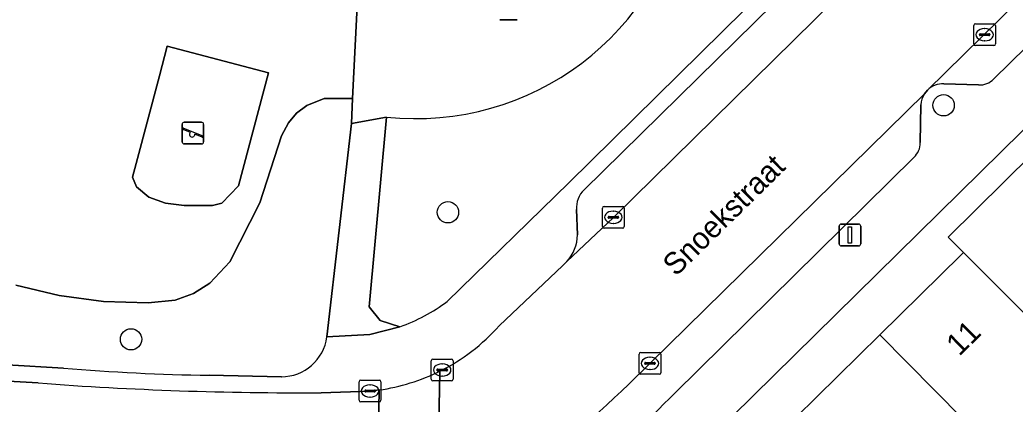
# Model space of a CAD drawing. Extents: x 160102 to 160934, y 382045 to 382923.
# Drawn here: x 160580.16 to 160625.81, y 382618.63 to 382636.26 of the extents above; entities that cross this region are included whole.
import ezdxf

# ---------------------------------------------------------------- set-up
doc = ezdxf.new("R2010")
doc.units = 0
for name, color, linetype in [('IMGEO_Boom', 7, 'Continuous'), ('IMGEO_Erf', 7, 'Continuous'), ('IMGEO_Groenvoorziening', 7, 'Continuous'), ('IMGEO_Kolk', 7, 'Continuous'), ('IMGEO_Lichtmast', 7, 'Continuous'), ('IMGEO_Openbare_ruimte_label', 7, 'Continuous'), ('IMGEO_Pand', 7, 'Continuous'), ('IMGEO_Pand_nummerreeks', 7, 'Continuous'), ('IMGEO_Parkeervlak_open', 7, 'Continuous'), ('IMGEO_Rijbaan_lokaal_open', 7, 'Continuous'), ('IMGEO_Speelvoorziening', 7, 'Continuous'), ('IMGEO_Terreindeel_zand', 7, 'Continuous'), ('IMGEO_Voetpad_open', 7, 'Continuous')]:
    doc.layers.add(name, color=color, linetype=linetype)

msp = doc.modelspace()

# ---------------------------------------------------------------- linework, layer by layer
at = {"layer": 'IMGEO_Boom'}
for centre in [(160622.528, 382632.346), (160599.793, 382627.438), (160585.259, 382621.606)]:
    msp.add_circle(centre, 0.489, dxfattribs=at)
at = {"layer": 'IMGEO_Erf'}
for points in [[(160661.762, 382636.708), (160646.97, 382651.686), (160602.42, 382607.815), (160569.084, 382609.884)], [(160615.748, 382618.012), (160619.597, 382621.808), (160623.314, 382625.474), (160623.44, 382625.598), (160622.74, 382626.3), (160626.598, 382630.102), (160630.432, 382633.883), (160634.268, 382637.664), (160638.105, 382641.447), (160641.954, 382645.241), (160645.935, 382649.166), (160652.312, 382642.745), (160648.748, 382639.239), (160648.326, 382638.824), (160644.465, 382635.025), (160640.62, 382631.244), (160636.792, 382627.478), (160632.941, 382623.689), (160635.111, 382621.515), (160631.378, 382617.789)]]:
    msp.add_lwpolyline(points, dxfattribs=at)
at = {"layer": 'IMGEO_Groenvoorziening'}
for points in [[(160599.766, 382623.349), (160605.335, 382628.789), (160619.427, 382642.677), (160618.419, 382643.7)], [(160579.978, 382624.096), (160581.967, 382623.615), (160583.995, 382623.344), (160586.041, 382623.287), (160587.285, 382623.409), (160588.122, 382623.714), (160588.878, 382624.187), (160589.787, 382625.163), (160591.169, 382627.872), (160592.162, 382630.942), (160592.478, 382631.541), (160592.856, 382631.979), (160593.316, 382632.329), (160594.118, 382632.656), (160595.423, 382632.661), (160595.751, 382639.325), (160586.256, 382639.661), (160583.249, 382639.767), (160582.276, 382639.706), (160581.243, 382639.535), (160580.233, 382639.257), (160579.258, 382638.875)], [(160594.247, 382621.716), (160595.367, 382631.512), (160595.423, 382632.661), (160594.118, 382632.656), (160593.316, 382632.329), (160592.856, 382631.979), (160592.478, 382631.541), (160592.162, 382630.942), (160591.169, 382627.872), (160589.787, 382625.163), (160588.878, 382624.187), (160588.122, 382623.714), (160587.285, 382623.409), (160586.041, 382623.287), (160583.995, 382623.344), (160581.967, 382623.615), (160579.978, 382624.096)], [(160596.974, 382631.804), (160596.18, 382623.098), (160596.69, 382622.474), (160597.589, 382622.18)], [(160574.391, 382620.748), (160582.154, 382620.287)], [(160588.841, 382619.954), (160592.153, 382619.887)]]:
    msp.add_lwpolyline(points, dxfattribs=at)
msp.add_lwpolyline([(160586.562, 382633.698), (160586.92, 382635.054), (160591.561, 382633.828), (160590.193, 382628.648), (160589.423, 382627.852), (160589, 382627.75), (160587.702, 382627.75), (160586.833, 382627.852), (160586.075, 382628.136), (160585.505, 382628.61), (160585.332, 382629.041), (160585.5, 382629.676)], close=True, dxfattribs=at)
for centre, radius, start, end in [((160598.31, 382644.385), 12.652, 263.9378, 350.1374), ((160594.884, 382629.83), 8.114, 289.4763, 306.9933), ((160592.148, 382622.006), 2.119, 270.1293, 352.1418), ((160590.256, 382715.672), 95.728, 265.14507, 269.15319)]:
    msp.add_arc(centre, radius, start, end, dxfattribs=at)
at = {"layer": 'IMGEO_Kolk'}
for p, q in [((160623.911, 382635.159), (160623.911, 382636.011)), ((160623.986, 382636.085), (160624.838, 382636.085)), ((160624.399, 382635.865), (160624.424, 382635.865)), ((160624.912, 382636.011), (160624.912, 382635.159)), ((160624.17, 382635.579), (160624.17, 382635.591)), ((160624.608, 382635.542), (160624.21, 382635.542)), ((160624.213, 382635.628), (160624.611, 382635.628)), ((160624.654, 382635.591), (160624.654, 382635.579)), ((160624.838, 382635.085), (160623.986, 382635.085)), ((160624.422, 382635.305), (160624.397, 382635.305)), ((160606.882, 382626.78), (160606.882, 382627.632)), ((160606.957, 382627.706), (160607.809, 382627.706)), ((160607.883, 382627.632), (160607.883, 382626.78)), ((160607.141, 382627.2), (160607.141, 382627.212)), ((160607.579, 382627.163), (160607.181, 382627.163)), ((160607.184, 382627.249), (160607.582, 382627.249)), ((160607.37, 382627.486), (160607.395, 382627.486)), ((160607.625, 382627.212), (160607.625, 382627.2)), ((160607.809, 382626.706), (160606.957, 382626.706)), ((160607.393, 382626.926), (160607.368, 382626.926)), ((160608.56, 382620.076), (160608.56, 382620.928)), ((160608.635, 382621.002), (160609.487, 382621.002)), ((160609.048, 382620.782), (160609.073, 382620.782)), ((160609.561, 382620.928), (160609.561, 382620.076)), ((160599.032, 382619.774), (160599.032, 382620.626)), ((160599.107, 382620.7), (160599.959, 382620.7)), ((160599.52, 382620.48), (160599.545, 382620.48)), ((160600.033, 382620.626), (160600.033, 382619.774)), ((160608.819, 382620.496), (160608.819, 382620.508)), ((160609.257, 382620.459), (160608.859, 382620.459)), ((160608.862, 382620.545), (160609.26, 382620.545)), ((160609.303, 382620.508), (160609.303, 382620.496)), ((160599.291, 382620.194), (160599.291, 382620.206)), ((160599.729, 382620.157), (160599.331, 382620.157)), ((160599.334, 382620.243), (160599.732, 382620.243)), ((160599.543, 382619.92), (160599.518, 382619.92)), ((160599.775, 382620.206), (160599.775, 382620.194)), ((160609.487, 382620.002), (160608.635, 382620.002)), ((160609.071, 382620.222), (160609.046, 382620.222)), ((160595.722, 382618.809), (160595.722, 382619.661)), ((160595.797, 382619.735), (160596.649, 382619.735)), ((160596.21, 382619.515), (160596.235, 382619.515)), ((160596.723, 382619.661), (160596.723, 382618.809)), ((160599.959, 382619.7), (160599.107, 382619.7)), ((160595.981, 382619.229), (160595.981, 382619.241)), ((160596.419, 382619.192), (160596.021, 382619.192)), ((160596.024, 382619.278), (160596.422, 382619.278)), ((160596.233, 382618.955), (160596.208, 382618.955)), ((160596.465, 382619.241), (160596.465, 382619.229)), ((160596.649, 382618.735), (160595.797, 382618.735))]:
    msp.add_line(p, q, dxfattribs=at)
for points in [[(160623.911, 382635.159), (160623.911, 382636.011)], [(160623.986, 382636.085), (160624.838, 382636.085)], [(160624.912, 382636.011), (160624.912, 382635.159)], [(160624.838, 382635.085), (160623.986, 382635.085)], [(160606.882, 382626.78), (160606.882, 382627.632)], [(160606.957, 382627.706), (160607.809, 382627.706)], [(160607.883, 382627.632), (160607.883, 382626.78)], [(160607.809, 382626.706), (160606.957, 382626.706)], [(160608.56, 382620.076), (160608.56, 382620.928)], [(160608.635, 382621.002), (160609.487, 382621.002)], [(160609.561, 382620.928), (160609.561, 382620.076)], [(160599.032, 382619.774), (160599.032, 382620.626)], [(160599.107, 382620.7), (160599.959, 382620.7)], [(160600.033, 382620.626), (160600.033, 382619.774)], [(160609.487, 382620.002), (160608.635, 382620.002)], [(160595.722, 382618.809), (160595.722, 382619.661)], [(160595.797, 382619.735), (160596.649, 382619.735)], [(160596.723, 382619.661), (160596.723, 382618.809)], [(160599.959, 382619.7), (160599.107, 382619.7)], [(160596.649, 382618.735), (160595.797, 382618.735)]]:
    msp.add_lwpolyline(points, dxfattribs=at)
for centre, radius, start, end in [((160623.988, 382636.009), 0.0765, 91.552, 178.448), ((160623.988, 382636.009), 0.0765, 91.552, 178.448), ((160624.836, 382636.009), 0.0765, 1.552, 88.448), ((160624.836, 382636.009), 0.0765, 1.552, 88.448), ((160624.21, 382635.588), 0.0403, 85.8775, 175.7526), ((160624.207, 382635.578), 0.0366, 178.938, 274.7102), ((160624.611, 382635.585), 0.043, 264.8664, 352.4533), ((160624.615, 382635.59), 0.0386, 1.7309, 96.639), ((160623.988, 382635.161), 0.0765, 181.552, 268.448), ((160623.988, 382635.161), 0.0765, 181.552, 268.448), ((160624.836, 382635.161), 0.0765, 271.552, 358.448), ((160624.836, 382635.161), 0.0765, 271.552, 358.448), ((160606.959, 382627.63), 0.0765, 91.552, 178.448), ((160606.959, 382627.63), 0.0765, 91.552, 178.448), ((160607.807, 382627.63), 0.0765, 1.552, 88.448), ((160607.807, 382627.63), 0.0765, 1.552, 88.448), ((160607.181, 382627.209), 0.0403, 85.8775, 175.7526), ((160607.178, 382627.199), 0.0366, 178.938, 274.7102), ((160607.582, 382627.206), 0.043, 264.8664, 352.4533), ((160607.586, 382627.211), 0.0386, 1.7309, 96.639), ((160606.959, 382626.782), 0.0765, 181.552, 268.448), ((160606.959, 382626.782), 0.0765, 181.552, 268.448), ((160607.807, 382626.782), 0.0765, 271.552, 358.448), ((160607.807, 382626.782), 0.0765, 271.552, 358.448), ((160608.637, 382620.926), 0.0765, 91.552, 178.448), ((160608.637, 382620.926), 0.0765, 91.552, 178.448), ((160609.485, 382620.926), 0.0765, 1.552, 88.448), ((160609.485, 382620.926), 0.0765, 1.552, 88.448), ((160599.109, 382620.624), 0.0765, 91.552, 178.448), ((160599.109, 382620.624), 0.0765, 91.552, 178.448), ((160599.957, 382620.624), 0.0765, 1.552, 88.448), ((160599.957, 382620.624), 0.0765, 1.552, 88.448), ((160608.859, 382620.505), 0.0403, 85.8775, 175.7526), ((160608.856, 382620.495), 0.0366, 178.938, 274.7102), ((160609.26, 382620.502), 0.043, 264.8664, 352.4533), ((160609.264, 382620.507), 0.0386, 1.7309, 96.639), ((160599.331, 382620.203), 0.0403, 85.8775, 175.7526), ((160599.328, 382620.193), 0.0366, 178.938, 274.7102), ((160599.732, 382620.2), 0.043, 264.8664, 352.4533), ((160599.736, 382620.205), 0.0386, 1.7309, 96.639), ((160608.637, 382620.078), 0.0765, 181.552, 268.448), ((160608.637, 382620.078), 0.0765, 181.552, 268.448), ((160609.485, 382620.078), 0.0765, 271.552, 358.448), ((160609.485, 382620.078), 0.0765, 271.552, 358.448), ((160595.799, 382619.659), 0.0765, 91.552, 178.448), ((160595.799, 382619.659), 0.0765, 91.552, 178.448), ((160596.647, 382619.659), 0.0765, 1.552, 88.448), ((160596.647, 382619.659), 0.0765, 1.552, 88.448), ((160599.109, 382619.776), 0.0765, 181.552, 268.448), ((160599.109, 382619.776), 0.0765, 181.552, 268.448), ((160599.957, 382619.776), 0.0765, 271.552, 358.448), ((160599.957, 382619.776), 0.0765, 271.552, 358.448), ((160596.021, 382619.238), 0.0403, 85.8775, 175.7526), ((160596.018, 382619.228), 0.0366, 178.938, 274.7102), ((160596.422, 382619.235), 0.043, 264.8664, 352.4533), ((160596.426, 382619.24), 0.0386, 1.7309, 96.639), ((160595.799, 382618.811), 0.0765, 181.552, 268.448), ((160595.799, 382618.811), 0.0765, 181.552, 268.448), ((160596.647, 382618.811), 0.0765, 271.552, 358.448), ((160596.647, 382618.811), 0.0765, 271.552, 358.448)]:
    msp.add_arc(centre, radius, start, end, dxfattribs=at)
for centre, major_axis, ratio, start_param, end_param in [((160624.398, 382635.585), (-0.387, 0.002), 0.722429, 4.712389, 7.853982), ((160624.423, 382635.585), (-0.39, 0.002), 0.717154, 1.570796, 4.712389), ((160607.369, 382627.206), (-0.387, 0.002), 0.722429, 4.712389, 7.853982), ((160607.394, 382627.206), (-0.39, 0.002), 0.717154, 1.570796, 4.712389), ((160609.047, 382620.502), (-0.387, 0.002), 0.722429, 4.712389, 7.853982), ((160609.072, 382620.502), (-0.39, 0.002), 0.717154, 1.570796, 4.712389), ((160599.519, 382620.2), (-0.387, 0.002), 0.722429, 4.712389, 7.853982), ((160599.544, 382620.2), (-0.39, 0.002), 0.717154, 1.570796, 4.712389), ((160596.209, 382619.235), (-0.387, 0.002), 0.722429, 4.712389, 7.853982), ((160596.234, 382619.235), (-0.39, 0.002), 0.717154, 1.570796, 4.712389)]:
    msp.add_ellipse(centre, major_axis=major_axis, ratio=ratio, start_param=start_param, end_param=end_param, dxfattribs=at)
at = {"layer": 'IMGEO_Lichtmast'}
for p, q in [((160617.735, 382625.994), (160617.735, 382626.794)), ((160617.735, 382626.794), (160617.735, 382625.994)), ((160617.835, 382626.894), (160618.625, 382626.894)), ((160618.625, 382626.894), (160617.835, 382626.894)), ((160618.725, 382626.794), (160618.725, 382625.994)), ((160618.725, 382625.994), (160618.725, 382626.794)), ((160618.625, 382625.894), (160617.835, 382625.894)), ((160617.835, 382625.894), (160618.625, 382625.894))]:
    msp.add_line(p, q, dxfattribs=at)
msp.add_lwpolyline([(160618.155, 382626.769), (160618.305, 382626.769), (160618.305, 382626.019), (160618.155, 382626.019), (160618.155, 382626.769)], dxfattribs=at)
for centre, start, end in [((160617.835, 382626.794), 90, 180), ((160617.835, 382626.794), 90, 180), ((160618.625, 382626.794), 0, 90), ((160618.625, 382626.794), 360, 90), ((160617.835, 382625.994), 180, 270), ((160617.835, 382625.994), 180, 270), ((160618.625, 382625.994), 270, 0), ((160618.625, 382625.994), 270, 0)]:
    msp.add_arc(centre, 0.1, start, end, dxfattribs=at)
at = {"layer": 'IMGEO_Pand'}
for points in [[(160626.598, 382630.102), (160622.74, 382626.3), (160623.44, 382625.598), (160629.798, 382619.222), (160631.311, 382617.722), (160631.378, 382617.789), (160635.111, 382621.515), (160632.941, 382623.689)], [(160623.44, 382625.598), (160623.314, 382625.474), (160619.597, 382621.808), (160625.931, 382615.409), (160625.913, 382615.391), (160628.352, 382612.917), (160632.322, 382616.832), (160631.378, 382617.789), (160631.311, 382617.722), (160629.798, 382619.222)], [(160619.597, 382621.808), (160615.748, 382618.012), (160622.09, 382611.63), (160624.353, 382609.396), (160628.007, 382612.999), (160625.778, 382615.258), (160625.913, 382615.391), (160625.931, 382615.409)]]:
    msp.add_lwpolyline(points, close=True, dxfattribs=at)
at = {"layer": 'IMGEO_Parkeervlak_open'}
for points in [[(160605.252, 382625.176), (160607.381, 382627.202), (160635.901, 382655.273), (160637.287, 382656.637)], [(160633.864, 382655.834), (160606.041, 382628.472)], [(160643.543, 382654.414), (160642.116, 382653.012), (160640.083, 382651.015), (160621.788, 382633.043)], [(160624.837, 382633.553), (160642.731, 382651.127)], [(160622.542, 382633.334), (160624.13, 382633.278)], [(160621.652, 382632.878), (160609.063, 382620.506)], [(160621.461, 382630.634), (160621.486, 382632.366)], [(160610.2, 382619.138), (160621.168, 382629.948)], [(160605.686, 382627.559), (160605.736, 382626.395)]]:
    msp.add_lwpolyline(points, dxfattribs=at)
for centre, radius, start, end in [((160624.163, 382634.24), 0.962, 268.0425, 314.4663), ((160622.508, 382632.3), 1.035, 88.1159, 134.0915), ((160622.491, 382632.323), 1.005, 146.5109, 177.5618), ((160620.489, 382630.644), 0.972, 314.3141, 359.4299), ((160606.885, 382627.618), 1.2, 134.6735, 182.8316), ((160603.865, 382626.432), 1.871, 317.8291, 358.8602), ((160566.603, 382662.625), 59.807, 308.23031, 315.23093), ((160563.564, 382665.202), 65.55, 310.42968, 315.35369)]:
    msp.add_arc(centre, radius, start, end, dxfattribs=at)
at = {"layer": 'IMGEO_Rijbaan_lokaal_open'}
for points in [[(160609.063, 382620.506), (160621.652, 382632.878), (160621.788, 382633.043), (160640.083, 382651.015), (160635.901, 382655.273), (160607.381, 382627.202), (160605.252, 382625.176), (160605.057, 382624.991), (160602.149, 382622.229)], [(160581, 382619.604), (160577.701, 382619.8), (160571.104, 382620.207), (160570.513, 382620.244)], [(160596.638, 382619.282), (160596.539, 382613.283), (160598.409, 382613.405), (160599.295, 382613.642), (160599.429, 382620.147)], [(160599.429, 382620.147), (160599.295, 382613.642)], [(160593.941, 382613.114), (160596.539, 382613.283), (160596.638, 382619.282)], [(160596.638, 382619.282), (160596.219, 382619.234), (160593.974, 382619.155)]]:
    msp.add_lwpolyline(points, dxfattribs=at)
for centre, radius, start, end in [((160595.308, 382628.348), 9.178, 296.6776, 318.1863), ((160566.603, 382662.625), 59.807, 308.23031, 315.23093), ((160595.321, 382628.465), 9.277, 278.1588, 296.2802), ((160592.98, 382778.093), 158.941, 265.6774, 270.35843)]:
    msp.add_arc(centre, radius, start, end, dxfattribs=at)
at = {"layer": 'IMGEO_Speelvoorziening'}
for p, q in [((160602.967, 382636.264), (160602.177, 382636.264)), ((160602.177, 382636.264), (160602.967, 382636.264)), ((160587.6, 382630.671), (160587.6, 382631.471)), ((160587.6, 382631.471), (160587.6, 382630.671)), ((160587.669, 382631.296), (160588.545, 382630.943)), ((160587.7, 382631.571), (160588.49, 382631.571)), ((160588.49, 382631.571), (160587.7, 382631.571)), ((160588.59, 382631.471), (160588.59, 382630.671)), ((160588.59, 382630.671), (160588.59, 382631.471)), ((160587.983, 382631.099), (160587.644, 382631.236)), ((160588.521, 382630.883), (160588.181, 382631.02)), ((160588.49, 382630.571), (160587.7, 382630.571)), ((160587.7, 382630.571), (160588.49, 382630.571))]:
    msp.add_line(p, q, dxfattribs=at)
for centre, radius, start, end in [((160587.7, 382631.471), 0.1, 90, 180), ((160587.7, 382631.471), 0.1, 90, 180), ((160587.657, 382631.266), 0.0327, 68.078, 248.078), ((160588.49, 382631.471), 0.1, 0, 90), ((160588.49, 382631.471), 0.1, 360, 90), ((160588.062, 382631.009), 0.12, 130.9928, 5.1632), ((160588.533, 382630.913), 0.0327, 248.078, 68.078), ((160587.7, 382630.671), 0.1, 180, 270), ((160587.7, 382630.671), 0.1, 180, 270), ((160588.49, 382630.671), 0.1, 270, 0), ((160588.49, 382630.671), 0.1, 270, 0)]:
    msp.add_arc(centre, radius, start, end, dxfattribs=at)
at = {"layer": 'IMGEO_Terreindeel_zand'}
msp.add_lwpolyline([(160586.562, 382633.698), (160585.5, 382629.676), (160585.332, 382629.041), (160585.505, 382628.61), (160586.075, 382628.136), (160586.833, 382627.852), (160587.702, 382627.75), (160589, 382627.75), (160589.423, 382627.852), (160590.193, 382628.648), (160591.561, 382633.828), (160586.92, 382635.054)], close=True, dxfattribs=at)
at = {"layer": 'IMGEO_Voetpad_open'}
for points in [[(160637.287, 382656.637), (160637.564, 382656.967), (160637.855, 382657.329), (160636.77, 382659.791), (160634.935, 382657.976), (160630.324, 382653.415), (160619.427, 382642.677), (160605.335, 382628.789), (160599.766, 382623.349)], [(160606.041, 382628.472), (160633.864, 382655.834)], [(160568.376, 382612.65), (160569.084, 382609.884), (160602.42, 382607.815), (160646.97, 382651.686)], [(160642.731, 382651.127), (160624.837, 382633.553)], [(160610.197, 382644.046), (160606.229, 382637.18), (160599.434, 382643.506), (160598.055, 382642.116), (160595.895, 382642.255), (160595.751, 382639.325), (160595.423, 382632.661), (160595.367, 382631.512), (160596.974, 382631.804)], [(160624.13, 382633.278), (160622.542, 382633.334)], [(160621.788, 382633.043), (160621.652, 382632.878)], [(160621.486, 382632.366), (160621.461, 382630.634)], [(160621.168, 382629.948), (160610.2, 382619.138)], [(160605.736, 382626.395), (160605.686, 382627.559)], [(160602.149, 382622.229), (160605.057, 382624.991)], [(160605.057, 382624.991), (160605.252, 382625.176)], [(160597.589, 382622.18), (160596.217, 382621.824), (160594.247, 382621.716)], [(160582.154, 382620.287), (160574.391, 382620.748), (160571.149, 382620.94), (160571.104, 382620.207), (160577.701, 382619.8), (160581, 382619.604)], [(160592.153, 382619.887), (160588.841, 382619.954)], [(160593.974, 382619.155), (160596.219, 382619.234), (160596.638, 382619.282)]]:
    msp.add_lwpolyline(points, dxfattribs=at)
msp.add_lwpolyline([(160596.217, 382621.824), (160597.589, 382622.18), (160596.69, 382622.474), (160596.18, 382623.098), (160596.974, 382631.804), (160595.367, 382631.512), (160594.247, 382621.716)], close=True, dxfattribs=at)
for centre, radius, start, end in [((160598.31, 382644.385), 12.652, 263.9378, 350.1374), ((160624.163, 382634.24), 0.962, 268.0425, 314.4663), ((160622.508, 382632.3), 1.035, 88.1159, 134.0915), ((160622.491, 382632.323), 1.005, 146.5109, 177.5618), ((160620.489, 382630.644), 0.972, 314.3141, 359.4299), ((160606.885, 382627.618), 1.2, 134.6735, 182.8316), ((160603.865, 382626.432), 1.871, 317.8291, 358.8602), ((160594.884, 382629.83), 8.114, 289.4763, 306.9933), ((160595.308, 382628.348), 9.178, 296.6776, 318.1863), ((160592.148, 382622.006), 2.119, 270.1293, 352.1418), ((160590.256, 382715.672), 95.728, 265.14507, 269.15319), ((160595.321, 382628.465), 9.277, 278.1588, 296.2802), ((160592.98, 382778.093), 158.941, 265.6774, 270.35843), ((160563.564, 382665.202), 65.55, 310.42968, 315.35369)]:
    msp.add_arc(centre, radius, start, end, dxfattribs=at)

# ---------------------------------------------------------------- texts
at = {"layer": 'IMGEO_Openbare_ruimte_label'}
msp.add_text('Snoekstraat', height=1, rotation=44.5138, dxfattribs=at).set_placement((160610.248, 382624.456))
at = {"layer": 'IMGEO_Pand_nummerreeks'}
msp.add_text('11', height=1, rotation=44.6048, dxfattribs=at).set_placement((160623.25, 382620.803))

doc.saveas('drawing.dxf')
